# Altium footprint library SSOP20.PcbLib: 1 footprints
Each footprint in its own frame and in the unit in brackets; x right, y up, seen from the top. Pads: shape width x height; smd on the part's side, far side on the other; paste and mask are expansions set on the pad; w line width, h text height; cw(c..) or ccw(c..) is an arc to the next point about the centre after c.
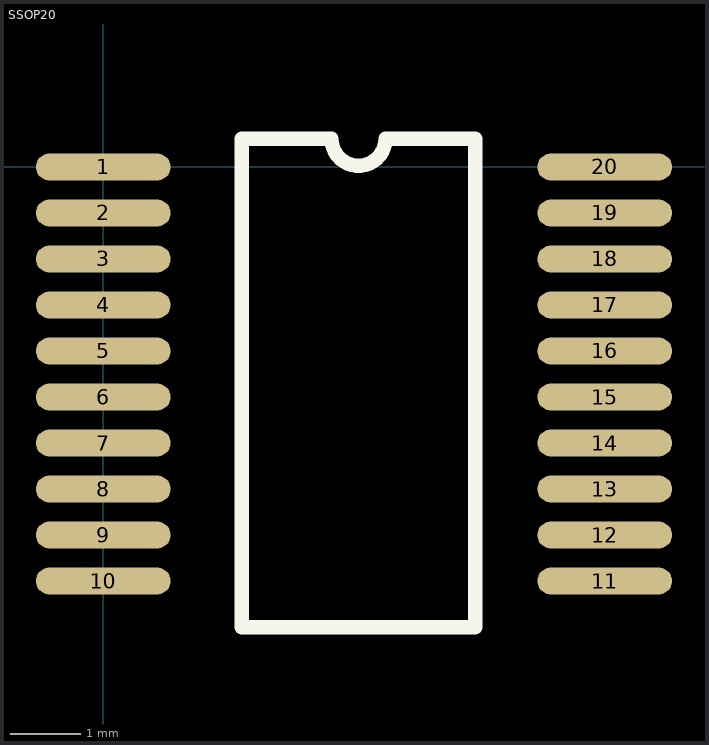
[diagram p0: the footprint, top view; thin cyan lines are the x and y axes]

## SSOP20 [mm]
pads (20):
  oval 1.905x0.38 smd: 1(0,0) 2(0,-0.65) 3(0,-1.3) 4(0,-1.95) 5(0,-2.6) 6(0,-3.25) 7(0,-3.9) 8(0,-4.55) 9(0,-5.2) 10(0,-5.85) 11(7.087,-5.85) 12(7.087,-5.2) 13(7.087,-4.55) 14(7.087,-3.9) 15(7.087,-3.25) 16(7.087,-2.6) 17(7.087,-1.95) 18(7.087,-1.3) 19(7.087,-0.65) 20(7.087,0)
Top Overlay:
  lines w0.203: 1.956,-6.502 1.956,0.398 3.226,0.398 ccw(c3.607,0.398) 3.988,0.398 5.258,0.398 5.258,-6.502 1.956,-6.502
